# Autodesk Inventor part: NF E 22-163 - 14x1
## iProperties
Component Type: 1
Library Location: C:\Program Files\Autodesk\Inventor 6\content
Library: local
SubLibrary: AFNOR
Family: 169
Member: 120
Member Major Revision: 1
Member Minor Revision: 2
Comments: To add or edit properties for Autodesk Inventor files, use iProperties.
Created: 2004-05
Part Number: NF E 22-163 - 14x1
Vendor: Autodesk Inc.
Document SubType Name: Modeling
Designer: David
Description: Rondelle élastique d'arrêt
Standard: NF E 22-163 14x1
Alert: To add or edit properties for Autodesk Inventor files, use iProperties.
Control State: 0
Master: False
Checked Out: False
Shininess: 64.0
Length Units: 11269
Angle Units: 11279
Time Units: 11290
Mass Units: 11283
Length Display Precision: 3
Angle Display Precision: 2
Compacted: True
Density: 0.0
Volumn: 0.0
Area: 0.0
PropertySet Name: Model Information
Author: David
Revision Number: 2
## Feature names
1. Corps [Extrusion]
